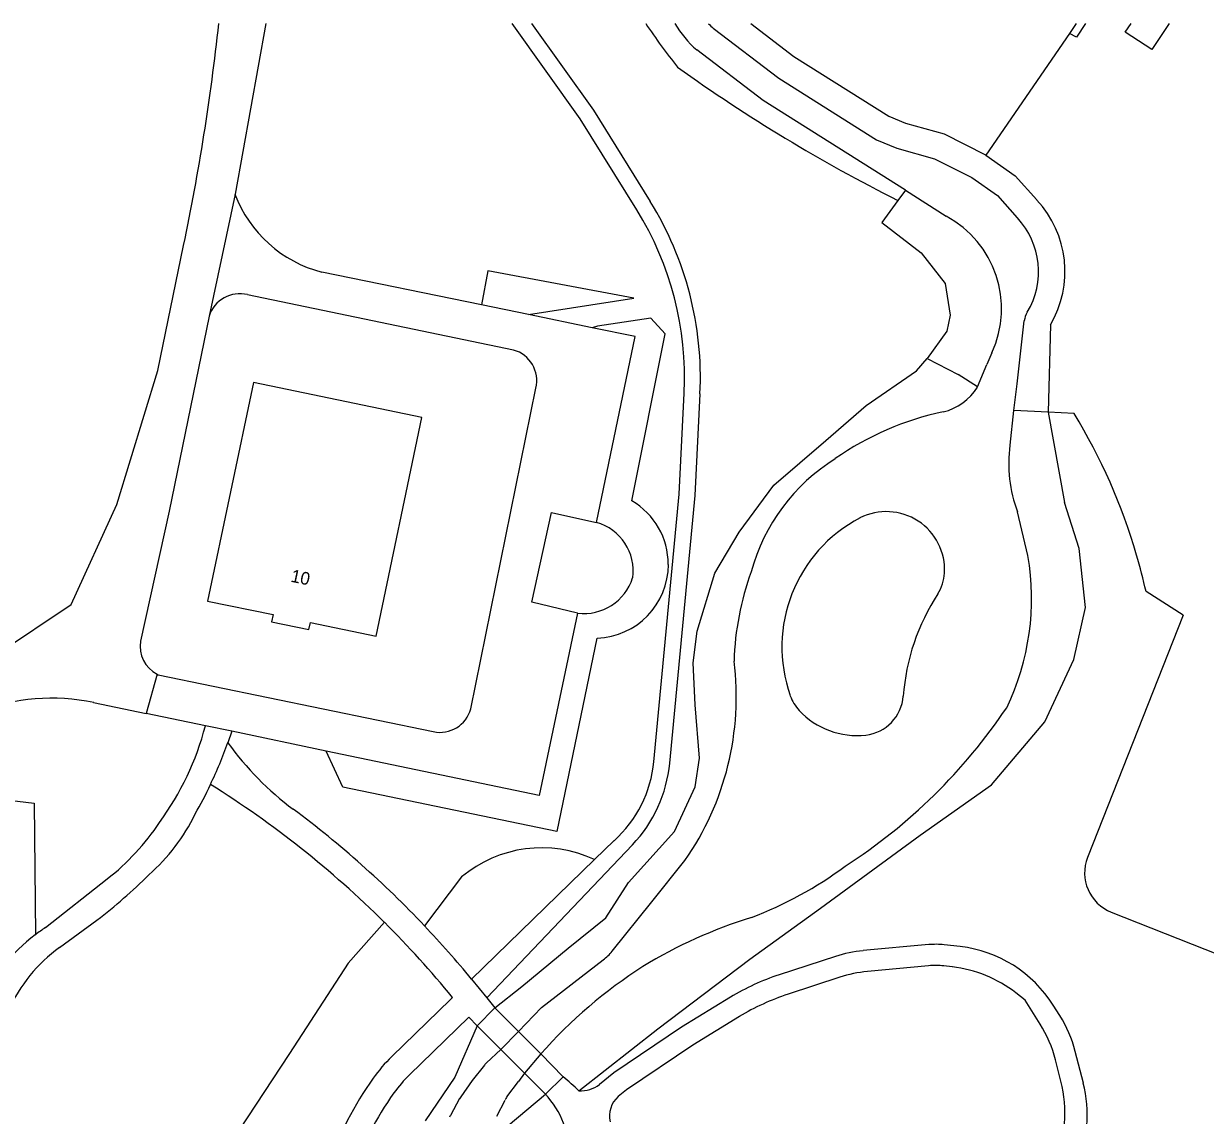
# Model space of a CAD drawing. Extents: x 194485 to 197793, y 468269 to 470822.
# Drawn here: x 194649.8 to 194761.7, y 470718.9 to 470822.3 of the extents above; entities that cross this region are included whole.
import ezdxf

# ---------------------------------------------------------------- set-up
doc = ezdxf.new("R2010")
doc.units = 0
for name, color, linetype in [('BGT grensvlak begroeid terreindeel', 7, 'Continuous'), ('BGT grensvlak onbegroeid terreindeel', 7, 'Continuous'), ('BGT grensvlak ondersteunend waterdeel LR', 7, 'Continuous'), ('BGT grensvlak overbruggingsdeel plus 1', 7, 'Continuous'), ('BGT grensvlak pand op maaiveld', 7, 'Continuous'), ('BGT grensvlak vegetatieobject', 7, 'Continuous'), ('BGT grensvlak waterdeel', 7, 'Continuous'), ('BGT grensvlak wegdeel', 7, 'Continuous'), ('BGT tekst huisnummerreeks', 7, 'Continuous')]:
    doc.layers.add(name, color=color, linetype=linetype)

msp = doc.modelspace()

# ---------------------------------------------------------------- linework, layer by layer
at = {"layer": 'BGT grensvlak begroeid terreindeel'}
for p, q in [((194732.6, 470805.54), (194731.07, 470803.46)), ((194737.08, 470797.67), (194737.55, 470794.66)), ((194737.55, 470794.66), (194737.23, 470793.16)), ((194737.23, 470793.16), (194735.37, 470790.55)), ((194746.83, 470785.47), (194748.37, 470776.92)), ((194691.29, 470741.45), (194687.78, 470736.81)), ((194692.75, 470727.36), (194690.65, 470722.49)), ((194690.65, 470722.49), (194687.83, 470718.36)), ((194695.7, 470717.9), (194699.23, 470720.89))]:
    msp.add_line(p, q, dxfattribs=at)
for points in [[(194731.07, 470803.46), (194734.81, 470800.57), (194737.08, 470797.67)], [(194707.1, 470740.93), (194711.44, 470745.76), (194713.42, 470750), (194713.82, 470752.7), (194713.42, 470757.75), (194713.21, 470761.73), (194713.58, 470764.75), (194715.28, 470770.23), (194717.57, 470774.1), (194720.86, 470778.58), (194725.77, 470782.78), (194729.6, 470786.12), (194734.37, 470789.41), (194735.37, 470790.55)], [(194702.4, 470721.19), (194709.87, 470727.08), (194718.59, 470733.65), (194725.28, 470738.49), (194734.71, 470745.42), (194741.46, 470750.18), (194746.5, 470756.15), (194749.25, 470762.05), (194750.35, 470766.98), (194749.75, 470772.57), (194748.37, 470776.92)], [(194635.76, 470750.23), (194650.81, 470748.43), (194650.93, 470735.98)], [(194694.45, 470729.06), (194696.98, 470731.09), (194701.39, 470734.7), (194704.96, 470737.59), (194707.1, 470740.93)], [(194683.98, 470737.16), (194680.54, 470733.3), (194674.99, 470724.73), (194664.67, 470709.03), (194658.77, 470698.47), (194655.21, 470697.06)]]:
    msp.add_lwpolyline(points, dxfattribs=at)
for centre, radius, start, end in [((194760.76, 470857.04), 62.57, 213.7402, 218.4293), ((194804.47, 470947.97), 159.54, 234.4634, 243.2253), ((194698.88, 470732.37), 11.84, 65.0059, 129.8907)]:
    msp.add_arc(centre, radius, start, end, dxfattribs=at)
at = {"layer": 'BGT grensvlak onbegroeid terreindeel'}
for p, q in [((194748.86, 470821.36), (194740.94, 470809.83)), ((194747.05, 470793.75), (194746.83, 470785.47)), ((194749.29, 470785.36), (194746.83, 470785.47)), ((194759.61, 470766.24), (194756.1, 470768.48)), ((194759.61, 470766.24), (194750.56, 470743.31)), ((194752.81, 470738.12), (194774.52, 470729.54))]:
    msp.add_line(p, q, dxfattribs=at)
for points in [[(194718.67, 470822.29), (194722.75, 470819.17), (194731.74, 470813.51), (194733.32, 470812.87), (194736.98, 470811.83), (194740.89, 470809.86), (194740.94, 470809.83)], [(194758.28, 470822.29), (194756.64, 470819.83), (194754.13, 470821.47), (194754.68, 470822.29)], [(194740.94, 470809.83), (194743.7, 470807.87), (194745.76, 470805.58)]]:
    msp.add_lwpolyline(points, dxfattribs=at)
for centre, radius, start, end in [((194738.48, 470798.8), 9.94, 329.4782, 42.9639), ((194701.08, 470756.09), 56.4, 16.3229, 31.2625), ((194700.72, 470755.99), 56.77, 12.7153, 16.3156), ((194754.28, 470741.84), 4, 158.4523, 248.4318)]:
    msp.add_arc(centre, radius, start, end, dxfattribs=at)
at = {"layer": 'BGT grensvlak ondersteunend waterdeel LR'}
for p, q in [((194733.32, 470806.51), (194732.6, 470805.54)), ((194735.37, 470790.55), (194738.3, 470789.04)), ((194740.13, 470787.87), (194738.3, 470789.04)), ((194746.83, 470785.47), (194743.59, 470785.63))]:
    msp.add_line(p, q, dxfattribs=at)
at = {"layer": 'BGT grensvlak overbruggingsdeel plus 1'}
for p, q in [((194692.75, 470727.36), (194694.45, 470729.06)), ((194694.45, 470729.06), (194696.67, 470726.82)), ((194696.67, 470726.82), (194698.78, 470724.69)), ((194700.91, 470722.53), (194698.78, 470724.69)), ((194699.23, 470720.89), (194700.91, 470722.53))]:
    msp.add_line(p, q, dxfattribs=at)
msp.add_lwpolyline([(194699.23, 470720.89), (194698.85, 470721.27), (194697.26, 470722.85), (194695.02, 470725.1), (194692.75, 470727.36)], dxfattribs=at)
at = {"layer": 'BGT grensvlak pand op maaiveld'}
msp.add_lwpolyline([(194683.21, 470764.25), (194687.52, 470784.99), (194671.59, 470788.29), (194667.24, 470767.59), (194673.44, 470766.3), (194673.3, 470765.63), (194676.84, 470764.89), (194676.98, 470765.55), (194683.21, 470764.25)], dxfattribs=at)
at = {"layer": 'BGT grensvlak vegetatieobject'}
for p, q in [((194749.48, 470822.29), (194748.86, 470821.36)), ((194702.29, 470766.42), (194702.27, 470766.43))]:
    msp.add_line(p, q, dxfattribs=at)
for points in [[(194750.35, 470822.29), (194749.51, 470821), (194748.86, 470821.36)], [(194697.62, 470794.72), (194707.59, 470796.27), (194693.79, 470798.88), (194693.17, 470795.64)], [(194707.42, 470777.08), (194710.57, 470792.9), (194709.22, 470794.39), (194704.17, 470793.64), (194703.64, 470793.48)], [(194704.11, 470764.07), (194700.32, 470745.75), (194680.03, 470749.96), (194678.48, 470753.38)]]:
    msp.add_lwpolyline(points, dxfattribs=at)
for centre, radius, start, end in [((194703.88, 470771.06), 6.98, 359.9871, 59.5498), ((194702.77, 470770.44), 4.77, 352.1471, 74.448), ((194703.88, 470771.06), 6.99, 271.9314, 0.0042), ((194702.84, 470771.28), 4.88, 263.4639, 342.2187)]:
    msp.add_arc(centre, radius, start, end, dxfattribs=at)
at = {"layer": 'BGT grensvlak waterdeel'}
for p, q in [((194733.32, 470806.51), (194737.17, 470804.05)), ((194743.89, 470788.17), (194744.57, 470794.14)), ((194741.51, 470791.1), (194741.03, 470789.99)), ((194740.13, 470787.87), (194741.03, 470789.99)), ((194743.59, 470785.63), (194743.89, 470788.17)), ((194743.22, 470782.35), (194743.59, 470785.63)), ((194744.91, 470771.89), (194743.94, 470776.03)), ((194695.02, 470725.1), (194696.67, 470726.82)), ((194695.02, 470725.1), (194693.65, 470723.85)), ((194695.58, 470720.62), (194696.67, 470722.09)), ((194691.09, 470720.45), (194690.23, 470718.87)), ((194694.64, 470718.79), (194695.4, 470720.32))]:
    msp.add_line(p, q, dxfattribs=at)
for points in [[(194715.12, 470821.85), (194721.33, 470817.12), (194730.59, 470811.28), (194732.51, 470810.5), (194736.07, 470809.49), (194739.6, 470807.71), (194742.02, 470805.99), (194743.91, 470803.89)], [(194733.32, 470806.51), (194719.85, 470814.99), (194713.56, 470819.79)], [(194705.55, 470734.42), (194709.3, 470739.1), (194712.44, 470743.01)], [(194696.67, 470726.82), (194698.85, 470729.09), (194704.7, 470733.59)], [(194698.78, 470724.69), (194697.26, 470722.85), (194696.67, 470722.09)], [(194693.45, 470723.62), (194692.29, 470722.18), (194691.21, 470720.63)]]:
    msp.add_lwpolyline(points, dxfattribs=at)
for centre, radius, start, end in [((194720.34, 470827.62), 10.35, 211.0374, 229.1275), ((194719.99, 470827.31), 7.32, 223.4023, 228.3428), ((194732.45, 470795.27), 9.97, 335.264, 61.7783), ((194738.48, 470798.8), 7.44, 328.827, 43.1169), ((194746.56, 470793.91), 2, 148.904, 173.461), ((194735.67, 470790.59), 5.23, 283.523, 328.5507), ((194742.84, 470757.85), 28.3, 102.1441, 124.8461), ((194755.75, 470780.58), 12.66, 171.9296, 201.0706), ((194736.37, 470765.55), 18.3, 121.9967, 164.7752), ((194735.42, 470763.24), 13.8, 117.6479, 199.5222), ((194731.5, 470770.53), 5.53, 356.9897, 116.7903), ((194721.42, 470767.81), 23.84, 334.3135, 9.8529), ((194744.45, 470761.04), 27.38, 160.101, 178.2028), ((194733.02, 470770.45), 4, 326.9575, 356.9593), ((194753.62, 470757.05), 20.57, 146.9557, 175.7458), ((194690.19, 470758.5), 27.11, 325.146, 7.1958), ((194726.18, 470759.96), 4, 199.5373, 222.9708), ((194729.12, 470758.87), 4, 276.5252, 355.7625), ((194728.72, 470762.33), 7.48, 222.9626, 276.5222), ((194698.62, 470787.29), 53.38, 302.9078, 326.0517), ((194705.18, 470772.99), 37.88, 290.9509, 306.3223), ((194732.93, 470692.47), 47.33, 107.4588, 121.1311), ((194701.6, 470737.6), 5.07, 307.6813, 321.1613), ((194734.15, 470693.18), 47.37, 122.8415, 138.3084), ((194695.03, 470722.35), 2.03, 132.6198, 141.1447), ((194692.86, 470719.47), 2.02, 144.8853, 150.9908), ((194697.18, 470719.45), 1.98, 143.5193, 153.7143), ((194691.9, 470717.94), 1.91, 150.9555, 156.2067)]:
    msp.add_arc(centre, radius, start, end, dxfattribs=at)
at = {"layer": 'BGT grensvlak wegdeel'}
for p, q in [((194672.74, 470822.29), (194669.84, 470806.13)), ((194702.53, 470813.27), (194696.07, 470822.29)), ((194697.91, 470822.29), (194703.78, 470814.1)), ((194707.88, 470804.65), (194702.53, 470813.27)), ((194703.78, 470814.1), (194709.15, 470805.44)), ((194669.84, 470806.13), (194667.38, 470794.57)), ((194662.53, 470789.43), (194664.97, 470801.28)), ((194693.17, 470795.64), (194678.05, 470798.74)), ((194696.2, 470791.36), (194671.03, 470796.61)), ((194697.62, 470794.72), (194693.17, 470795.64)), ((194703.64, 470793.48), (194697.62, 470794.72)), ((194658.66, 470776.73), (194662.53, 470789.43)), ((194692.16, 470757.39), (194698.32, 470787.74)), ((194711.9, 470777.7), (194712.37, 470787.29)), ((194713.86, 470787.22), (194713.39, 470777.59)), ((194709.5, 470752.37), (194711.9, 470777.7)), ((194713.39, 470777.59), (194710.99, 470752.23)), ((194654.31, 470767.27), (194658.66, 470776.73)), ((194638.94, 470756.94), (194654.31, 470767.27)), ((194662.45, 470760.65), (194661.41, 470756.94)), ((194656.45, 470757.98), (194661.41, 470756.94)), ((194667.03, 470755.77), (194661.41, 470756.94)), ((194669.55, 470755.25), (194667.03, 470755.77)), ((194669.55, 470755.25), (194669.17, 470754.17)), ((194678.48, 470753.38), (194669.55, 470755.25)), ((194703.89, 470743.1), (194705.73, 470744.89)), ((194707.47, 470744.49), (194693.69, 470729.99)), ((194692.23, 470731.77), (194703.89, 470743.1)), ((194651.9, 470736.66), (194657.73, 470741.26)), ((194653.22, 470734.77), (194656.76, 470737.37)), ((194735.53, 470735.05), (194729.31, 470734.47)), ((194738.5, 470734.86), (194736.97, 470735.03)), ((194726.68, 470733.92), (194721.36, 470732.18)), ((194735.51, 470733.04), (194729.72, 470732.5)), ((194737.75, 470732.93), (194736.95, 470733.02)), ((194692.23, 470731.77), (194693.69, 470729.99)), ((194727.09, 470731.95), (194722.2, 470730.35)), ((194693.69, 470729.99), (194694.45, 470729.06)), ((194747.93, 470728.32), (194747.3, 470729.31)), ((194750.16, 470721.93), (194749.38, 470724.93)), ((194748.04, 470722.11), (194747.52, 470724.13))]:
    msp.add_line(p, q, dxfattribs=at)
for points in [[(194667.38, 470794.57), (194663.59, 470776.1), (194660.88, 470763.8)], [(194704.05, 470775.03), (194707.74, 470792.64), (194703.64, 470793.48)], [(194702.27, 470766.43), (194697.93, 470767.48), (194699.8, 470775.97), (194703.91, 470775.07), (194704.05, 470775.03)], [(194702.27, 470766.43), (194698.63, 470749.18), (194678.48, 470753.38)], [(194662.45, 470760.65), (194662.55, 470760.6), (194688.61, 470755.22)], [(194746.07, 470727.52), (194744.65, 470729.79), (194743.76, 470730.47)], [(194684.68, 470724.43), (194690.24, 470729.85), (194690.44, 470730.03)], [(194716.75, 470730.05), (194712.1, 470727.21), (194705.69, 470722.9), (194704.35, 470721.79)], [(194686.35, 470722.71), (194691.96, 470728.18), (194692.75, 470727.36)], [(194717.59, 470728.22), (194713.18, 470725.53), (194706.89, 470721.3), (194706.12, 470720.65)]]:
    msp.add_lwpolyline(points, dxfattribs=at)
for centre, radius, start, end in [((194451.89, 470845.9), 217.7, 348.1724, 353.7716), ((194681.08, 470810.38), 12.02, 200.6615, 255.3911), ((194682.29, 470788.77), 31.61, 357.1841, 31.8274), ((194682.29, 470788.77), 30.11, 357.1863, 31.8301), ((194670.29, 470793.64), 3.06, 76.0831, 162.3133), ((194695.42, 470788.48), 2.99, 345.7848, 74.8383), ((194663.85, 470763.31), 3, 170.6626, 242.351), ((194652.49, 470738.6), 19.78, 78.4377, 110.6631), ((194689.25, 470758.15), 3, 257.6751, 345.2507), ((194640.53, 470762.75), 27.41, 323.9504, 345.2518), ((194627.25, 470769.38), 44.59, 334.5429, 340.0592), ((194692.48, 470770.84), 28.66, 215.5679, 233.3043), ((194698.03, 470753.46), 11.52, 311.9266, 354.5887), ((194698.03, 470753.46), 13.02, 316.4537, 354.5915), ((194627.42, 470769.32), 44.42, 330.4638, 334.5108), ((194617.73, 470670.52), 93.96, 45.1662, 58.0056), ((194649.47, 470755.52), 18.47, 311.3705, 333.9977), ((194617.77, 470670.57), 96.39, 43.4163, 53.3126), ((194643.74, 470759.19), 22.74, 307.9698, 326.4384), ((194626.64, 470776.74), 49.58, 307.4117, 314.9634), ((194617.8, 470670.58), 93.87, 39.299, 45.1731), ((194661.07, 470722.54), 16.84, 127.0278, 155.849), ((194661.11, 470722.51), 16.88, 123.0595, 127.0829), ((194617.18, 470670.02), 97.19, 39.4478, 43.4115), ((194661.91, 470722.81), 14.79, 126.0089, 156.0384), ((194736.18, 470728.11), 6.96, 83.457, 95.3519), ((194737.14, 470722.93), 12, 32.0887, 83.4791), ((194730.41, 470722.56), 11.96, 95.2865, 108.1629), ((194730.84, 470720.49), 12.06, 95.3384, 108.111), ((194736.16, 470726.11), 6.96, 83.452, 95.3568), ((194736.39, 470721), 12.01, 52.0916, 83.4668), ((194728.22, 470711.25), 22.03, 108.1498, 121.3863), ((194729.05, 470709.44), 22, 108.1461, 121.4011), ((194737.74, 470721.93), 12.03, 14.4482, 32.0715), ((194735.91, 470721.14), 11.99, 14.4238, 32.0959), ((194695.16, 470713.68), 15.02, 134.2759, 144.5723), ((194709.81, 470703.25), 33, 144.5647, 160.774), ((194695.14, 470713.7), 12.58, 134.2669, 144.5854), ((194657.9, 470673.33), 65.35, 47.0803, 48.8346), ((194702.55, 470724.19), 3, 267.0305, 306.8409), ((194736.42, 470719.12), 12, 335.6991, 14.4268), ((194738.53, 470718.94), 12, 335.6967, 14.4293), ((194709.81, 470703.25), 30.6, 144.5607, 160.7709), ((194692.74, 470714.94), 8.8, 0.0057, 42.5102), ((194707.8, 470718.79), 2.51, 132.0769, 192.2776)]:
    msp.add_arc(centre, radius, start, end, dxfattribs=at)

# ---------------------------------------------------------------- texts
at = {"layer": 'BGT tekst huisnummerreeks'}
msp.add_text('10', height=1.2, rotation=348.2, dxfattribs=at).set_placement((194675.05, 470769.43))

doc.saveas('drawing.dxf')
